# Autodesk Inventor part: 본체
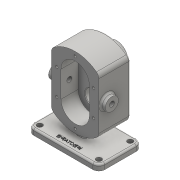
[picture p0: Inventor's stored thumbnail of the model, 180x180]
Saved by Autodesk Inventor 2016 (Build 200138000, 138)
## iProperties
Created: 2019-03
Part Number: 본체
Material: Generic
Document SubType Name: Modeling
Designer: 2-PC11
Density: 1 g/cm^3
Appearance: Default
Author: 2-PC11
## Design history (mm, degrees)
sketch "스케치1"
  geometry: L1 (-60, -36.5)-(60, -36.5); L2 (60, -36.5)-(60, 36.5); L3 (60, 36.5)-(-60, 36.5); L4 (-60, 36.5)-(-60, -36.5); L5 (-60, -36.5)-(60, 36.5); L6 (60, -36.5)-(-60, 36.5); 1 further point
  constraints: 12 end point, 2 midpoint, 2 parallel, 1 horizontal, 1 perpendicular
  dimensions: "d0" = 73 distance of L1.end L2.end; "d1" = 120 distance of L2.end L3.end
extrude "돌출1" new body sketch "스케치1" distance "d2" = 10; taper "d3" = 0 deg
sketch "스케치2"
  geometry: L1 (60, 36.5)-(-60, 36.5) reference; L2 (-6, 36.5)-(6, 36.5); L3 (6, 36.5)-(6, -6.5); L4 (6, -6.5)-(-6, -6.5); L5 (-6, -6.5)-(-6, 36.5); 2 further points
  constraints: 8 end point, 2 parallel, 1 horizontal, 1 midpoint, 1 perpendicular, 1 point on line, 1 vertical alignment
  dimensions: "d4" = 12 distance between parallel lines of L3 L5; "d5" = 43 distance of L4.end L2.start
extrude "돌출2" join sketch "스케치2" distance "d6" = 68; taper "d7" = 0 deg
sketch "스케치3"
  geometry: L1 (100, -122.721)-(100, -33.279); L2 (20, -122.721)-(20, -33.279); L3 (120, 0)-(0, 0) reference; L4 (100, -78)-(20, -78); A1 r 60 centre (60, -78) between (100, -33.279) and (20, -33.279); A2 r 60 centre (60, -78) between (20, -122.721) and (100, -122.721); 4 further points
  constraints: 6 end point, 5 midpoint, 4 point on circle, 4 vertical alignment, 2 centre point, 2 vertical
  dimensions: "d8" = 60 radius of A2; "d9" = 60 radius of A1; "d10" = 80 distance between parallel lines of L2 L1; "d11" = 40 distance from line of point (60, 0) L1; "d12" = 138 dimension on A2 L3; "d14" = 78 distance from line of point (60, 0) L4
extrude "돌출3" join sketch "스케치3" distance "d15" = 53; taper "d16" = 0 deg
sketch "스케치4"
  geometry: L1 (100, 33.279)-(100, 122.721) reference; L2 (20, 122.721)-(20, 33.279) reference; L3 (60, 100)-(60, 56); L4 (36, 100)-(36, 56); L5 (84, 56)-(84, 100); A1 r 60 centre (60, 78) between (100, 122.721) and (20, 122.721) reference; A2 r 60 centre (60, 78) between (20, 33.279) and (100, 33.279) reference; A3 r 24 centre (60, 100) between (84, 100) and (36, 100); A4 r 24 centre (60, 56) between (36, 56) and (84, 56); 2 further points
  constraints: 8 end point, 4 point on circle, 4 tangent, 2 centre point, 1 coincident, 1 midpoint, 1 parallel, 1 vertical
  dimensions: "d17" = 24 radius of A3; "d18" = 22 distance of A1.centre L3.start
extrude "돌출4" cut sketch "스케치4" distance "d19" = 29; taper "d20" = 0 deg
sketch "스케치5"
  geometry: L1 (36, 56)-(36, 100) reference; L2 (84, 100)-(84, 56) reference; C1 r 12.5 at (60, 100); C2 r 12.5 at (60, 56); A1 r 24 centre (60, 56) between (36, 56) and (84, 56) reference; A2 r 24 centre (60, 100) between (84, 100) and (36, 100) reference; 1 further point
  constraints: 2 centre point, 2 coincident, 1 equal radius
  dimensions: "d21" = 25 diameter of C1
extrude "돌출5" cut sketch "스케치5" distance "d22" = 15; taper "d23" = 0 deg
sketch "스케치6"
  geometry: C1 r 8.5 at (0, 0); C2 r 12.5 at (0, 0) reference; 1 further point
  constraints: 1 centre point, 1 concentric
  dimensions: "d24" = 17 diameter of C1
extrude "돌출6" cut sketch "스케치6" stored distance "d25" = 15; taper "d26" = 0 deg
sketch "스케치7"
  geometry: C1 r 19 at (60, -100); C2 r 8.5 at (60, -100) reference; 1 further point
  constraints: 1 centre point, 1 concentric
  dimensions: "d27" = 38 diameter of C1
extrude "돌출7" join sketch "스케치7" distance "d28" = 17; taper "d29" = 0 deg
chamfer "모따기3" distance "d40" = 1; stored, may be unused: second distance "d41" = 2, angle "d42" = 45 deg
fillet "모깎기2" dims "d43" = 10
sketch "스케치9"
  geometry: L1 (118, -73)-(118, 0) reference; L2 (80, -53)-(0, -53) reference; C1 r 11 at (40, -39); 1 further point
  constraints: 1 centre point
  dimensions: "d44" = 78 distance from line of L1 C1.centre; "d45" = 14 distance from line of C1.centre L2; "d46" = 22 diameter of C1
extrude "돌출9" join sketch "스케치9" distance "d47" = 8; taper "d48" = 0 deg
fillet "모깎기3" dims "d49" = 3
hole "구멍1" diameter "d52" = 8.376; stored, may be unused: countersink angle "d56" = 90 deg, drill point angle "d58" = 118 deg; dims "d50" = 10, "d51" = 10, "d53" = 50, "d54" = 4, "d55" = 2, "d57" = 27.3
hole "구멍2" diameter "d61" = 8.376; stored, may be unused: countersink angle "d65" = 90 deg, drill point angle "d67" = 118 deg; dims "d59" = 10, "d60" = 10, "d62" = 50, "d63" = 4, "d64" = 2, "d66" = 27.3
fillet "모깎기4" dims "d68" = 3
fillet "모깎기5" dims "d69" = 3
fillet "모깎기6" dims "d70" = 10
fillet "모깎기7" dims "d71" = 3
fillet "모깎기8" dims "d72" = 3
sketch "스케치10"
  geometry: L1 (60, 100)-(60, 56); L2 (29, 100)-(29, 56); L3 (91, 56)-(91, 100); L4 (10, 0)-(110, 0) reference; A1 r 31 centre (60, 100) between (91, 100) and (29, 100); A2 r 31 centre (60, 56) between (29, 56) and (91, 56); 10 further points
  constraints: 8 end point, 6 point on circle, 5 coincident, 4 tangent, 2 centre point, 2 midpoint, 1 parallel, 1 vertical, 1 vertical alignment
  dimensions: "d73" = 31 radius of A1; "d74" = 22 distance of point (60, 78) L1.start; "d75" = 78 distance from line of L4 point (60, 78)
hole "구멍3" sketch "스케치10" at (60, 131), (29, 100), (29, 56), (60, 25), (91, 56), (91, 100) diameter "d76" = 4.134; stored, may be unused: countersink angle "d80" = 90 deg, drill point angle "d82" = 118 deg; dims "d77" = 10, "d78" = 4, "d79" = 2, "d81" = 12
hole "구멍4" diameter "d85" = 9; stored, may be unused: countersink angle "d89" = 90 deg, drill point angle "d91" = 0 deg; dims "d83" = 10, "d84" = 10, "d86" = 10, "d87" = 4, "d88" = 2, "d90" = 12
hole "구멍5" diameter "d94" = 9; stored, may be unused: countersink angle "d98" = 90 deg, drill point angle "d100" = 0 deg; dims "d92" = 10, "d93" = 10, "d95" = 10, "d96" = 4, "d97" = 2, "d99" = 12
hole "구멍6" diameter "d103" = 9; stored, may be unused: countersink angle "d107" = 90 deg, drill point angle "d109" = 0 deg; dims "d101" = 10, "d102" = 10, "d104" = 10, "d105" = 4, "d106" = 2, "d108" = 12
hole "구멍7" diameter "d112" = 9; stored, may be unused: countersink angle "d116" = 90 deg, drill point angle "d118" = 0 deg; dims "d110" = 10, "d111" = 10, "d113" = 10, "d114" = 4, "d115" = 2, "d117" = 12
sketch "스케치11"
  geometry: L1 (-23.597, -23.498)-(23.597, -23.498); L2 (23.597, -23.498)-(23.597, -29.502); L3 (23.597, -29.502)-(-23.597, -29.502); L4 (-23.597, -29.502)-(-23.597, -23.498); L5 (-23.597, -26.5)-(23.597, -26.5); L6 (0, -23.498)-(0, -29.502); L7 (-50, -36.5)-(50, -36.5) reference; L8 (-60, 26.5)-(-60, -26.5) reference; 1 further point
  constraints: 4 end point, 4 midpoint, 2 other
  dimensions: "d119" = 10 distance between parallel lines of L7 L5; "d120" = 60 distance between parallel lines of L6 L8
feature "엠보싱1" sketch "스케치11" dims "d0" = 73, "d1" = 120, "d8" = 60, "d9" = 60, "d10" = 80, "d11" = 40, "d12" = 138, "d14" = 78, "d121" = 0.5, "d122" = 0
sketch "스케치12"
  geometry: L1 (27.5, 91.5)-(27.5, 108.5) reference; L2 (53.5, 108.5)-(53.5, 91.5) reference; L3 (27.5, 100)-(53.5, 100); L4 (46.2, 100)-(46.2, 113.5); L5 (46.7, 114)-(52.8, 114); L6 (52.8, 114)-(53.5, 114.404); L7 (53.5, 114.404)-(53.5, 100); A1 r 0.5 centre (46.7, 113.5) between (46.7, 114) and (46.2, 113.5); 1 further point
  constraints: 10 end point, 2 midpoint, 2 point on circle, 2 point on line, 2 tangent, 1 centre point, 1 collinear, 1 perpendicular, 1 vertical
  dimensions: "d123" = 0.7 horizontal distance of L6.end L5.end; "d124" = 7.3 distance between parallel lines of L2 L4; "d125" = 28 diameter of L5 L3; "d126" = 30 deg angle of L5 L6; "d127" = 0.5 radius of A1
revolve "회전1" sketch "스케치12" stored, may be unused: angle "d128" = 90 deg
node "솔리드1"
mirror "대칭1"
node "투영된 루프1"
node "투영된 루프2"
